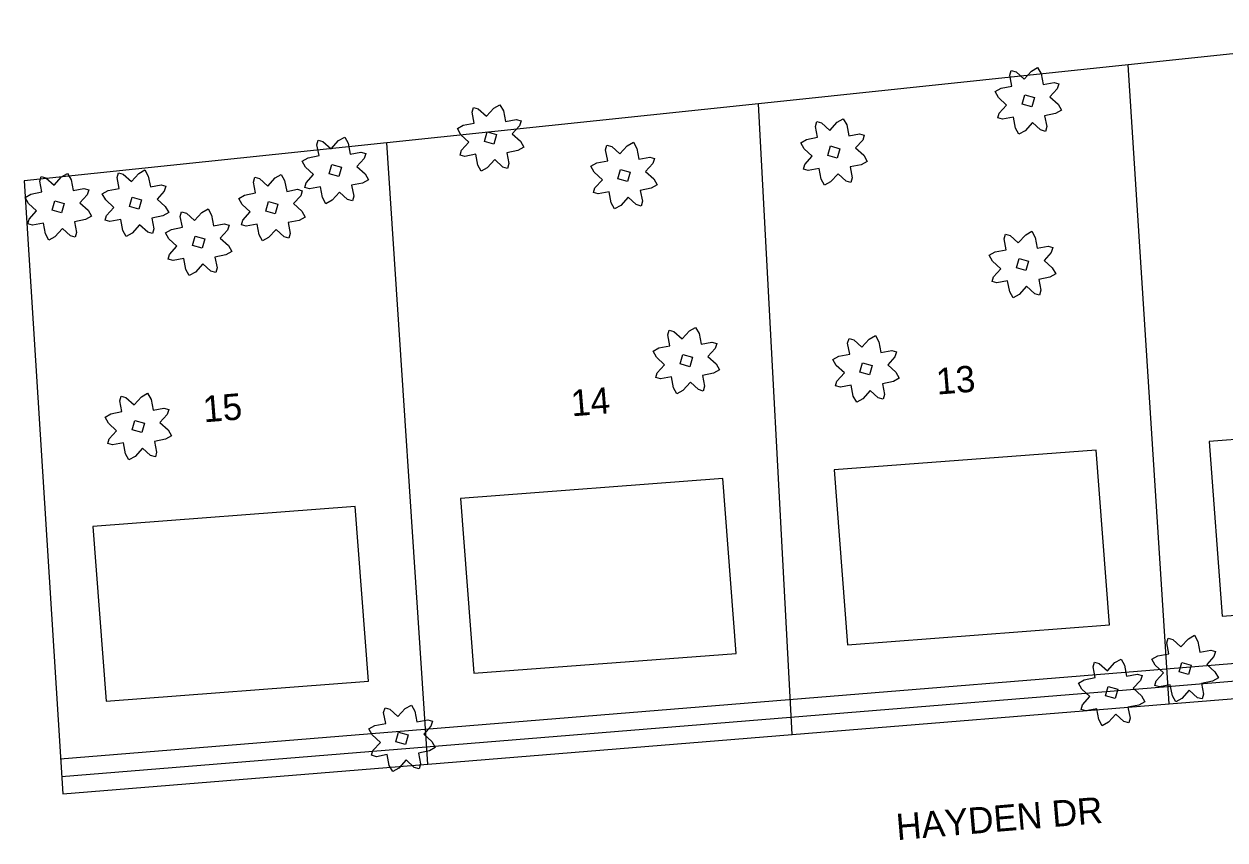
# Model space of a CAD drawing. Extents: x 1810019 to 1811399, y 1074962 to 1076105.
# Drawn here: x 1810273.9 to 1810548, y 1075841.6 to 1076027.7 of the extents above; entities that cross this region are included whole.
import ezdxf

# ---------------------------------------------------------------- set-up
doc = ezdxf.new("R2010")
doc.units = 0
for name, color, linetype in [('Environmental-New trees', 7, 'Continuous'), ('Property-Buildings', 7, 'Continuous'), ('Roadway-Land lines', 7, 'Continuous'), ('Roadway-Sidewalks', 7, 'Continuous'), ('Text-Property owner', 7, 'Continuous'), ('Text-Route label', 7, 'Continuous')]:
    doc.layers.add(name, color=color, linetype=linetype)

msp = doc.modelspace()

# ---------------------------------------------------------------- linework, layer by layer
at = {"layer": 'Environmental-New trees'}
for points in [[(1810496.14, 1076006.28), (1810496.44, 1076007.36), (1810498.13, 1076009.22), (1810496.27, 1076010.91), (1810495.5, 1076012.3), (1810496.85, 1076013.06), (1810499.35, 1076013.55), (1810498.88, 1076016.02), (1810499.19, 1076017.11), (1810500.27, 1076016.8), (1810502.13, 1076015.11), (1810503.82, 1076016.97), (1810505.21, 1076017.75), (1810505.99, 1076016.36), (1810506.46, 1076013.89), (1810508.94, 1076014.36), (1810510.02, 1076014.06), (1810509.65, 1076012.9), (1810508.02, 1076011.11), (1810509.88, 1076009.42), (1810510.66, 1076008.03), (1810509.31, 1076007.27), (1810506.8, 1076006.78), (1810507.27, 1076004.31), (1810506.97, 1076003.22), (1810505.88, 1076003.53), (1810504.02, 1076005.22), (1810502.33, 1076003.36), (1810500.94, 1076002.58), (1810500.16, 1076003.97), (1810499.69, 1076006.44), (1810497.22, 1076005.97)], [(1810502.3, 1076011.55), (1810504.47, 1076010.94), (1810503.85, 1076008.78), (1810501.69, 1076009.39)], [(1810373.42, 1075997.82), (1810373.73, 1075998.91), (1810375.42, 1076000.77), (1810373.56, 1076002.46), (1810372.78, 1076003.85), (1810374.14, 1076004.61), (1810376.64, 1076005.1), (1810376.17, 1076007.57), (1810376.48, 1076008.65), (1810377.56, 1076008.35), (1810379.42, 1076006.66), (1810381.11, 1076008.52), (1810382.5, 1076009.29), (1810383.28, 1076007.91), (1810383.75, 1076005.44), (1810386.22, 1076005.91), (1810387.31, 1076005.6), (1810386.94, 1076004.45), (1810385.31, 1076002.66), (1810387.17, 1076000.97), (1810387.95, 1075999.58), (1810386.6, 1075998.82), (1810384.09, 1075998.33), (1810384.56, 1075995.86), (1810384.26, 1075994.77), (1810383.17, 1075995.08), (1810381.31, 1075996.77), (1810379.62, 1075994.91), (1810378.23, 1075994.13), (1810377.45, 1075995.52), (1810376.98, 1075997.99), (1810374.51, 1075997.52)], [(1810451.77, 1075994.6), (1810452.08, 1075995.69), (1810453.77, 1075997.55), (1810451.91, 1075999.24), (1810451.13, 1076000.63), (1810452.48, 1076001.39), (1810454.99, 1076001.88), (1810454.52, 1076004.35), (1810454.82, 1076005.43), (1810455.91, 1076005.13), (1810457.77, 1076003.44), (1810459.46, 1076005.3), (1810460.85, 1076006.08), (1810461.63, 1076004.69), (1810462.1, 1076002.22), (1810464.57, 1076002.69), (1810465.65, 1076002.38), (1810465.28, 1076001.23), (1810463.65, 1075999.44), (1810465.52, 1075997.75), (1810466.29, 1075996.36), (1810464.94, 1075995.6), (1810462.43, 1075995.11), (1810462.91, 1075992.64), (1810462.6, 1075991.55), (1810461.52, 1075991.86), (1810459.66, 1075993.55), (1810457.96, 1075991.69), (1810456.58, 1075990.91), (1810455.8, 1075992.3), (1810455.33, 1075994.77), (1810452.85, 1075994.3)], [(1810379.59, 1076003.1), (1810381.75, 1076002.49), (1810381.14, 1076000.32), (1810378.98, 1076000.94)], [(1810337.99, 1075990.4), (1810338.3, 1075991.49), (1810339.99, 1075993.35), (1810338.13, 1075995.04), (1810337.35, 1075996.43), (1810338.7, 1075997.19), (1810341.21, 1075997.68), (1810340.74, 1076000.15), (1810341.04, 1076001.23), (1810342.12, 1076000.93), (1810343.99, 1075999.24), (1810345.68, 1076001.1), (1810347.07, 1076001.87), (1810347.85, 1076000.49), (1810348.32, 1075998.02), (1810350.79, 1075998.49), (1810351.87, 1075998.18), (1810351.5, 1075997.03), (1810349.87, 1075995.24), (1810351.74, 1075993.55), (1810352.51, 1075992.16), (1810351.16, 1075991.4), (1810348.65, 1075990.91), (1810349.13, 1075988.44), (1810348.82, 1075987.35), (1810347.74, 1075987.66), (1810345.88, 1075989.35), (1810344.18, 1075987.49), (1810342.8, 1075986.71), (1810342.02, 1075988.1), (1810341.54, 1075990.57), (1810339.07, 1075990.1)], [(1810403.87, 1075989.25), (1810404.17, 1075990.33), (1810405.87, 1075992.19), (1810404.01, 1075993.88), (1810403.23, 1075995.27), (1810404.58, 1075996.03), (1810407.09, 1075996.52), (1810406.62, 1075998.99), (1810406.92, 1076000.08), (1810408, 1075999.77), (1810409.87, 1075998.08), (1810411.56, 1075999.94), (1810412.95, 1076000.72), (1810413.72, 1075999.33), (1810414.2, 1075996.86), (1810416.67, 1075997.33), (1810417.75, 1075997.03), (1810417.38, 1075995.87), (1810415.75, 1075994.08), (1810417.61, 1075992.39), (1810418.39, 1075991), (1810417.04, 1075990.24), (1810414.53, 1075989.75), (1810415.01, 1075987.28), (1810414.7, 1075986.19), (1810413.62, 1075986.5), (1810411.76, 1075988.19), (1810410.06, 1075986.33), (1810408.67, 1075985.55), (1810407.9, 1075986.94), (1810407.42, 1075989.41), (1810404.95, 1075988.94)], [(1810457.93, 1075999.88), (1810460.1, 1075999.27), (1810459.49, 1075997.11), (1810457.32, 1075997.72)], [(1810292.4, 1075982.95), (1810292.7, 1075984.03), (1810294.39, 1075985.89), (1810292.53, 1075987.58), (1810291.76, 1075988.97), (1810293.11, 1075989.73), (1810295.62, 1075990.22), (1810295.14, 1075992.69), (1810295.45, 1075993.78), (1810296.53, 1075993.47), (1810298.39, 1075991.78), (1810300.09, 1075993.64), (1810301.47, 1075994.42), (1810302.25, 1075993.03), (1810302.72, 1075990.56), (1810305.2, 1075991.03), (1810306.28, 1075990.72), (1810305.91, 1075989.57), (1810304.28, 1075987.78), (1810306.14, 1075986.09), (1810306.92, 1075984.7), (1810305.57, 1075983.94), (1810303.06, 1075983.45), (1810303.53, 1075980.98), (1810303.23, 1075979.89), (1810302.14, 1075980.2), (1810300.28, 1075981.89), (1810298.59, 1075980.03), (1810297.2, 1075979.25), (1810296.42, 1075980.64), (1810295.95, 1075983.11), (1810293.48, 1075982.64)], [(1810344.15, 1075995.68), (1810346.32, 1075995.07), (1810345.71, 1075992.9), (1810343.54, 1075993.52)], [(1810410.03, 1075994.52), (1810412.2, 1075993.91), (1810411.59, 1075991.75), (1810409.42, 1075992.36)], [(1810274.76, 1075982.11), (1810275.07, 1075983.19), (1810276.76, 1075985.06), (1810274.9, 1075986.75), (1810274.12, 1075988.14), (1810275.48, 1075988.9), (1810277.98, 1075989.39), (1810277.51, 1075991.86), (1810277.82, 1075992.94), (1810278.9, 1075992.64), (1810280.76, 1075990.94), (1810282.45, 1075992.81), (1810283.84, 1075993.58), (1810284.62, 1075992.2), (1810285.09, 1075989.72), (1810287.56, 1075990.2), (1810288.65, 1075989.89), (1810288.28, 1075988.74), (1810286.65, 1075986.95), (1810288.51, 1075985.25), (1810289.29, 1075983.87), (1810287.93, 1075983.11), (1810285.43, 1075982.61), (1810285.9, 1075980.14), (1810285.6, 1075979.06), (1810284.51, 1075979.37), (1810282.65, 1075981.06), (1810280.96, 1075979.2), (1810279.57, 1075978.42), (1810278.79, 1075979.81), (1810278.32, 1075982.28), (1810275.85, 1075981.81)], [(1810323.52, 1075981.91), (1810323.82, 1075983), (1810325.52, 1075984.86), (1810323.65, 1075986.55), (1810322.88, 1075987.94), (1810324.23, 1075988.7), (1810326.74, 1075989.19), (1810326.26, 1075991.66), (1810326.57, 1075992.74), (1810327.65, 1075992.44), (1810329.51, 1075990.74), (1810331.21, 1075992.61), (1810332.59, 1075993.38), (1810333.37, 1075992), (1810333.84, 1075989.52), (1810336.32, 1075990), (1810337.4, 1075989.69), (1810337.03, 1075988.54), (1810335.4, 1075986.75), (1810337.26, 1075985.05), (1810338.04, 1075983.67), (1810336.69, 1075982.91), (1810334.18, 1075982.42), (1810334.65, 1075979.94), (1810334.35, 1075978.86), (1810333.26, 1075979.17), (1810331.4, 1075980.86), (1810329.71, 1075979), (1810328.32, 1075978.22), (1810327.54, 1075979.61), (1810327.07, 1075982.08), (1810324.6, 1075981.61)], [(1810280.93, 1075987.39), (1810283.09, 1075986.78), (1810282.48, 1075984.61), (1810280.32, 1075985.22)], [(1810298.56, 1075988.22), (1810300.73, 1075987.61), (1810300.12, 1075985.45), (1810297.95, 1075986.06)], [(1810329.68, 1075987.19), (1810331.85, 1075986.58), (1810331.24, 1075984.41), (1810329.07, 1075985.02)], [(1810306.8, 1075974.05), (1810307.11, 1075975.13), (1810308.8, 1075977), (1810306.94, 1075978.69), (1810306.16, 1075980.08), (1810307.52, 1075980.84), (1810310.02, 1075981.33), (1810309.55, 1075983.8), (1810309.86, 1075984.88), (1810310.94, 1075984.58), (1810312.8, 1075982.88), (1810314.49, 1075984.75), (1810315.88, 1075985.52), (1810316.66, 1075984.14), (1810317.13, 1075981.66), (1810319.6, 1075982.14), (1810320.69, 1075981.83), (1810320.32, 1075980.68), (1810318.69, 1075978.89), (1810320.55, 1075977.19), (1810321.33, 1075975.81), (1810319.98, 1075975.05), (1810317.47, 1075974.55), (1810317.94, 1075972.08), (1810317.64, 1075971), (1810316.55, 1075971.31), (1810314.69, 1075973), (1810313, 1075971.14), (1810311.61, 1075970.36), (1810310.83, 1075971.75), (1810310.36, 1075974.22), (1810307.89, 1075973.75)], [(1810494.8, 1075968.95), (1810495.11, 1075970.03), (1810496.8, 1075971.89), (1810494.94, 1075973.58), (1810494.16, 1075974.97), (1810495.51, 1075975.73), (1810498.02, 1075976.22), (1810497.55, 1075978.69), (1810497.85, 1075979.78), (1810498.93, 1075979.47), (1810500.8, 1075977.78), (1810502.49, 1075979.64), (1810503.88, 1075980.42), (1810504.66, 1075979.03), (1810505.13, 1075976.56), (1810507.6, 1075977.03), (1810508.68, 1075976.72), (1810508.31, 1075975.57), (1810506.68, 1075973.78), (1810508.55, 1075972.09), (1810509.32, 1075970.7), (1810507.97, 1075969.94), (1810505.46, 1075969.45), (1810505.94, 1075966.98), (1810505.63, 1075965.89), (1810504.55, 1075966.2), (1810502.69, 1075967.89), (1810500.99, 1075966.03), (1810499.61, 1075965.25), (1810498.83, 1075966.64), (1810498.35, 1075969.11), (1810495.88, 1075968.64)], [(1810312.97, 1075979.33), (1810315.13, 1075978.72), (1810314.52, 1075976.55), (1810312.36, 1075977.16)], [(1810500.96, 1075974.22), (1810503.13, 1075973.61), (1810502.52, 1075971.45), (1810500.35, 1075972.06)], [(1810418.08, 1075947.05), (1810418.38, 1075948.14), (1810420.08, 1075950), (1810418.22, 1075951.69), (1810417.44, 1075953.08), (1810418.79, 1075953.84), (1810421.3, 1075954.33), (1810420.82, 1075956.8), (1810421.13, 1075957.88), (1810422.21, 1075957.58), (1810424.07, 1075955.89), (1810425.77, 1075957.75), (1810427.15, 1075958.52), (1810427.93, 1075957.14), (1810428.41, 1075954.66), (1810430.88, 1075955.14), (1810431.96, 1075954.83), (1810431.59, 1075953.68), (1810429.96, 1075951.89), (1810431.82, 1075950.19), (1810432.6, 1075948.81), (1810431.25, 1075948.05), (1810428.74, 1075947.56), (1810429.21, 1075945.08), (1810428.91, 1075944), (1810427.83, 1075944.31), (1810425.96, 1075946), (1810424.27, 1075944.14), (1810422.88, 1075943.36), (1810422.1, 1075944.75), (1810421.63, 1075947.22), (1810419.16, 1075946.75)], [(1810459.1, 1075945.16), (1810459.41, 1075946.25), (1810461.1, 1075948.11), (1810459.24, 1075949.8), (1810458.46, 1075951.19), (1810459.82, 1075951.95), (1810462.32, 1075952.44), (1810461.85, 1075954.91), (1810462.16, 1075955.99), (1810463.24, 1075955.69), (1810465.1, 1075953.99), (1810466.79, 1075955.86), (1810468.18, 1075956.63), (1810468.96, 1075955.25), (1810469.43, 1075952.77), (1810471.9, 1075953.25), (1810472.99, 1075952.94), (1810472.62, 1075951.79), (1810470.99, 1075950), (1810472.85, 1075948.3), (1810473.63, 1075946.92), (1810472.28, 1075946.16), (1810469.77, 1075945.67), (1810470.24, 1075943.19), (1810469.94, 1075942.11), (1810468.85, 1075942.42), (1810466.99, 1075944.11), (1810465.3, 1075942.25), (1810463.91, 1075941.47), (1810463.13, 1075942.86), (1810462.66, 1075945.33), (1810460.19, 1075944.86)], [(1810424.24, 1075952.33), (1810426.41, 1075951.72), (1810425.8, 1075949.55), (1810423.63, 1075950.16)], [(1810465.27, 1075950.44), (1810467.43, 1075949.83), (1810466.82, 1075947.66), (1810464.66, 1075948.27)], [(1810293.03, 1075932.01), (1810293.33, 1075933.09), (1810295.02, 1075934.95), (1810293.16, 1075936.65), (1810292.39, 1075938.03), (1810293.74, 1075938.79), (1810296.25, 1075939.29), (1810295.77, 1075941.76), (1810296.08, 1075942.84), (1810297.16, 1075942.53), (1810299.02, 1075940.84), (1810300.72, 1075942.7), (1810302.1, 1075943.48), (1810302.88, 1075942.09), (1810303.35, 1075939.62), (1810305.83, 1075940.09), (1810306.91, 1075939.79), (1810306.54, 1075938.63), (1810304.91, 1075936.84), (1810306.77, 1075935.15), (1810307.55, 1075933.76), (1810306.2, 1075933), (1810303.69, 1075932.51), (1810304.16, 1075930.04), (1810303.86, 1075928.96), (1810302.77, 1075929.26), (1810300.91, 1075930.96), (1810299.22, 1075929.09), (1810297.83, 1075928.32), (1810297.05, 1075929.7), (1810296.58, 1075932.18), (1810294.11, 1075931.7)], [(1810299.19, 1075937.29), (1810301.36, 1075936.68), (1810300.75, 1075934.51), (1810298.58, 1075935.12)], [(1810531.92, 1075876.81), (1810532.23, 1075877.89), (1810533.92, 1075879.76), (1810532.06, 1075881.45), (1810531.28, 1075882.84), (1810532.64, 1075883.59), (1810535.14, 1075884.09), (1810534.67, 1075886.56), (1810534.98, 1075887.64), (1810536.06, 1075887.34), (1810537.92, 1075885.64), (1810539.61, 1075887.5), (1810541, 1075888.28), (1810541.78, 1075886.89), (1810542.25, 1075884.42), (1810544.72, 1075884.9), (1810545.81, 1075884.59), (1810545.44, 1075883.43), (1810543.81, 1075881.65), (1810545.67, 1075879.95), (1810546.45, 1075878.57), (1810545.1, 1075877.81), (1810542.59, 1075877.31), (1810543.06, 1075874.84), (1810542.76, 1075873.76), (1810541.67, 1075874.06), (1810539.81, 1075875.76), (1810538.12, 1075873.9), (1810536.73, 1075873.12), (1810535.95, 1075874.51), (1810535.48, 1075876.98), (1810533.01, 1075876.51)], [(1810515.15, 1075871.36), (1810515.45, 1075872.45), (1810517.15, 1075874.31), (1810515.29, 1075876), (1810514.51, 1075877.39), (1810515.86, 1075878.15), (1810518.37, 1075878.64), (1810517.9, 1075881.11), (1810518.2, 1075882.19), (1810519.28, 1075881.89), (1810521.14, 1075880.19), (1810522.84, 1075882.06), (1810524.23, 1075882.83), (1810525, 1075881.45), (1810525.48, 1075878.97), (1810527.95, 1075879.45), (1810529.03, 1075879.14), (1810528.66, 1075877.99), (1810527.03, 1075876.2), (1810528.89, 1075874.5), (1810529.67, 1075873.12), (1810528.32, 1075872.36), (1810525.81, 1075871.86), (1810526.29, 1075869.39), (1810525.98, 1075868.31), (1810524.9, 1075868.62), (1810523.04, 1075870.31), (1810521.34, 1075868.45), (1810519.95, 1075867.67), (1810519.18, 1075869.06), (1810518.7, 1075871.53), (1810516.23, 1075871.06)], [(1810538.09, 1075882.09), (1810540.25, 1075881.48), (1810539.64, 1075879.31), (1810537.48, 1075879.92)], [(1810521.31, 1075876.64), (1810523.48, 1075876.03), (1810522.87, 1075873.86), (1810520.7, 1075874.47)], [(1810353.21, 1075860.91), (1810353.52, 1075861.99), (1810355.21, 1075863.85), (1810353.35, 1075865.55), (1810352.57, 1075866.93), (1810353.93, 1075867.69), (1810356.43, 1075868.18), (1810355.96, 1075870.66), (1810356.27, 1075871.74), (1810357.35, 1075871.43), (1810359.21, 1075869.74), (1810360.9, 1075871.6), (1810362.29, 1075872.38), (1810363.07, 1075870.99), (1810363.54, 1075868.52), (1810366.01, 1075868.99), (1810367.1, 1075868.69), (1810366.73, 1075867.53), (1810365.1, 1075865.74), (1810366.96, 1075864.05), (1810367.74, 1075862.66), (1810366.39, 1075861.9), (1810363.88, 1075861.41), (1810364.35, 1075858.94), (1810364.05, 1075857.86), (1810362.96, 1075858.16), (1810361.1, 1075859.86), (1810359.41, 1075857.99), (1810358.02, 1075857.22), (1810357.24, 1075858.6), (1810356.77, 1075861.08), (1810354.3, 1075860.6)], [(1810359.38, 1075866.19), (1810361.54, 1075865.58), (1810360.93, 1075863.41), (1810358.77, 1075864.02)]]:
    msp.add_lwpolyline(points, close=True, dxfattribs=at)
at = {"layer": 'Property-Buildings'}
for points in [[(1810607.18, 1075897.17), (1810604.15, 1075937.05), (1810544.32, 1075932.5), (1810547.35, 1075892.62)], [(1810521.64, 1075890.66), (1810518.6, 1075930.54), (1810458.78, 1075925.99), (1810461.81, 1075886.11)], [(1810436.37, 1075884.17), (1810433.34, 1075924.06), (1810373.51, 1075919.51), (1810376.54, 1075879.62)], [(1810352.47, 1075877.79), (1810349.44, 1075917.68), (1810289.61, 1075913.12), (1810292.65, 1075873.24)]]:
    msp.add_lwpolyline(points, close=True, dxfattribs=at)
at = {"layer": 'Roadway-Land lines'}
for p, q in [((1810614.28, 1076027.7), (1810525.87, 1076018.4)), ((1810525.87, 1076018.4), (1810441.52, 1076009.53)), ((1810535.19, 1075872.66), (1810525.87, 1076018.4)), ((1810441.52, 1076009.53), (1810356.71, 1076000.61)), ((1810449.16, 1075865.66), (1810441.52, 1076009.53)), ((1810356.71, 1076000.61), (1810273.89, 1075991.9)), ((1810366.03, 1075858.89), (1810356.71, 1076000.61)), ((1810273.89, 1075991.9), (1810282.78, 1075852.12)), ((1810535.19, 1075872.66), (1810621.22, 1075879.66)), ((1810449.16, 1075865.66), (1810535.19, 1075872.66)), ((1810366.03, 1075858.89), (1810449.16, 1075865.66)), ((1810282.78, 1075852.12), (1810366.03, 1075858.89))]:
    msp.add_line(p, q, dxfattribs=at)
at = {"layer": 'Roadway-Sidewalks'}
for p, q in [((1810534.54, 1075880.63), (1810620.57, 1075887.63)), ((1810534.86, 1075876.64), (1810620.89, 1075883.65)), ((1810448.51, 1075873.63), (1810534.54, 1075880.63)), ((1810448.83, 1075869.65), (1810534.86, 1075876.64)), ((1810365.38, 1075866.87), (1810448.51, 1075873.63)), ((1810365.7, 1075862.88), (1810448.83, 1075869.65)), ((1810282.14, 1075860.09), (1810365.38, 1075866.87)), ((1810282.46, 1075856.11), (1810365.7, 1075862.88))]:
    msp.add_line(p, q, dxfattribs=at)

# ---------------------------------------------------------------- texts
at = {"layer": 'Text-Property owner'}
for s, p in [('13', (1810482.28, 1075943.17)), ('14', (1810398.93, 1075938.21)), ('15', (1810314.96, 1075936.84))]:
    msp.add_text(s, height=6, rotation=4.6517, dxfattribs=at).set_placement(p)
at = {"layer": 'Text-Route label'}
msp.add_text('HAYDEN DR', height=6, rotation=4.814, dxfattribs=at).set_placement((1810473.16, 1075841.55))

doc.saveas('drawing.dxf')
